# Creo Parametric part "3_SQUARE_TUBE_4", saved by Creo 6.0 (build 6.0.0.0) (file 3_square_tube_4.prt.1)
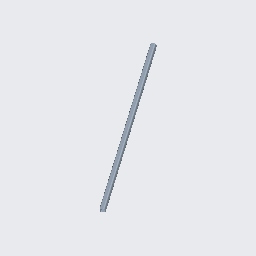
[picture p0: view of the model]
Units: Custom; MM, KILOGRAM, SECS
Materials in the file: STEEL

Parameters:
  BUW_NAME = "SQUARE TUBE"
  BUW_TYPE = "DIN EN 10219"
  BUW_SIZE = "25x25x3.0"
  BUW_LENGTH_STR = "910"
  PTC_MATERIAL_NAME = "STEEL"
  BUW_PROFIL_TYPE = "square_tube"
  BUW_PROFILE_PATH = "parts//profiles/steel_beams_mm/"
  BUW_PROFILE_NAME_LANG = "SQUARE TUBE"
  BUW_TAB_SEL_INFO = "-2 TYPE DIN_EN_10219-1997 SIZE_DINEN_10219 25x25x3.0"
  NAMING = "SQUARE TUBE"
  DESIGNATION = "DIN EN 10219 25x25x3.0 x 910"
  PROFIL_RASTER_POS = "X_0"
  BUW_OBJECT_ROLE = "PROFIL_SYSTEM_BORE_END_POINTS"
  PRO_UNIT_SYS = "Custom"

Other parameters: BUW_LENGTH, LENGTH, BUW_LENGTH_Z_MIN_PARAM, D8, D93, D94, d26, d8, d93, d94, d98, D98, SHEAR_MODULUS, THERM_EXPANSION_REF_TEMPERATURE, STRUCTURAL_DAMPING_COEFFICIENT, STRESS_LIMIT_FOR_TENSION, STRESS_LIMIT_FOR_COMPRESSION, STRESS_LIMIT_FOR_SHEAR, EMISSIVITY

Created from: SQUARE_TUBE.PRT

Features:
  1. datum plane "YZ"
  2. datum plane "XZ"
  3. datum plane "XY"
  4. coordinate system
  5. coordinate system
  6. coordinate system
  7. coordinate system
  8. datum plane "DTM3"
  9. datum plane "DTM4"
  10. datum plane "DTM5"
  11. protrusion
  12. round
  13. round
  14. datum axis
  15. datum point "PNT0"
  16. datum point

Other named items: PROFIL_CUT_QUILT, PROFILE_LENGTH_DIM, CONTACT_SURF_3, CONTACT_SURF_2, CONTACT_SURF_1, CONTACT_SURF_0, E, START_SURFACE, END_SURFACE, SIDE_SURF_3, SIDE_SURF_0, SIDE_SURF_1, SIDE_SURF_2, EDGE_7_S, EDGE_7_E, EDGE_1_S, EDGE_1_E, EDGE_3_S, EDGE_3_E, EDGE_5_S, EDGE_5_E, EDGE_6_S, EDGE_4_S, EDGE_2_S, EDGE_0_S, EDGE_6_E, EDGE_4_E, EDGE_2_E, EDGE_0_E, CS0, CS_S, CS_E, CS3

Named dimensions: X_ROT_S, Y_ROT_S, Z_OFF_S, X_ROT_E, Y_ROT_E, Z_OFF_E, PC_L, BUW_LENGTH_Z_MIN, BUW_LENGTH_DIM

Layers: 00_PROFIL_DATUM, 00_PROFIL_DRW_HIDE, 00_PROFIL_END_CSYS, 00_PROFIL_GEOMETRY, 00_PROFIL_QUILT, 00_PROFIL_SIZE_NOTE

Surfaces: 16 plane, 12 cylinder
